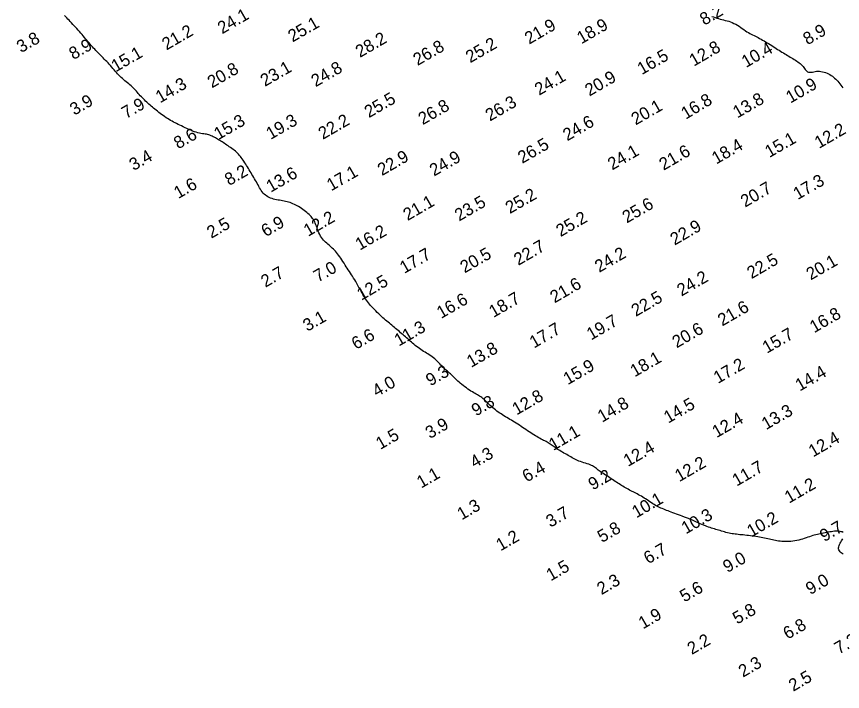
# Model space of a CAD drawing. Extents: x 3024098 to 3056816, y 418252 to 509144.
# Drawn here: x 3027058 to 3027391.3, y 419770.4 to 420042.8 of the extents above; entities that cross this region are included whole.
import ezdxf

# ---------------------------------------------------------------- set-up
doc = ezdxf.new("R2010")
doc.units = 0
doc.layers.add('V-CHAN-CONT-EL10', color=7, linetype='Continuous')
doc.layers.add('V-TOPO-SOUN-0911', color=7, linetype='Continuous')

msp = doc.modelspace()

# ---------------------------------------------------------------- linework, layer by layer
at = {"layer": 'V-CHAN-CONT-EL10'}
for points in [[(3027391.64, 419834.55), (3027391.28, 419834.72), (3027390.85, 419834.85), (3027390.38, 419834.95), (3027389.85, 419835.02), (3027389.29, 419835.04), (3027388.71, 419835.03), (3027388.12, 419834.99), (3027387.5, 419834.93), (3027386.88, 419834.85), (3027386.24, 419834.74), (3027385.61, 419834.63), (3027384.97, 419834.51), (3027384.34, 419834.39), (3027383.71, 419834.27), (3027383.09, 419834.15), (3027382.47, 419834.03), (3027381.85, 419833.9), (3027381.23, 419833.77), (3027380.6, 419833.61), (3027379.97, 419833.45), (3027379.33, 419833.26), (3027378.68, 419833.05), (3027378.02, 419832.82), (3027377.34, 419832.58), (3027376.65, 419832.34), (3027375.94, 419832.1), (3027375.22, 419831.87), (3027374.47, 419831.65), (3027373.71, 419831.46), (3027372.94, 419831.29), (3027372.14, 419831.14), (3027371.35, 419831.03), (3027370.55, 419830.94), (3027369.76, 419830.88), (3027368.98, 419830.84), (3027368.23, 419830.83), (3027367.5, 419830.85), (3027366.81, 419830.9), (3027366.14, 419830.97), (3027365.5, 419831.05), (3027364.88, 419831.16), (3027364.27, 419831.28), (3027363.67, 419831.41), (3027363.06, 419831.55), (3027362.45, 419831.69), (3027361.83, 419831.83), (3027361.2, 419831.97), (3027360.55, 419832.11), (3027359.9, 419832.25), (3027359.23, 419832.38), (3027358.54, 419832.51), (3027357.85, 419832.64), (3027357.14, 419832.76), (3027356.41, 419832.88), (3027355.67, 419832.99), (3027354.93, 419833.09), (3027354.19, 419833.19), (3027353.45, 419833.28), (3027352.71, 419833.36), (3027351.99, 419833.44), (3027351.29, 419833.51), (3027350.6, 419833.58), (3027349.93, 419833.64), (3027349.27, 419833.71), (3027348.64, 419833.78), (3027348.01, 419833.85), (3027347.39, 419833.93), (3027346.77, 419834.03), (3027346.16, 419834.14), (3027345.55, 419834.27), (3027344.94, 419834.42), (3027344.33, 419834.57), (3027343.73, 419834.74), (3027343.13, 419834.92), (3027342.54, 419835.09), (3027341.95, 419835.27), (3027341.37, 419835.44), (3027340.8, 419835.61), (3027340.23, 419835.77), (3027339.66, 419835.94), (3027339.08, 419836.11), (3027338.5, 419836.29), (3027337.9, 419836.48), (3027337.29, 419836.7), (3027336.65, 419836.93), (3027336, 419837.19), (3027335.31, 419837.47), (3027334.61, 419837.77), (3027333.89, 419838.08), (3027333.14, 419838.41), (3027332.38, 419838.75), (3027331.6, 419839.09), (3027330.8, 419839.43), (3027329.99, 419839.77), (3027329.17, 419840.11), (3027328.35, 419840.45), (3027327.53, 419840.77), (3027326.71, 419841.09), (3027325.91, 419841.4), (3027325.12, 419841.7), (3027324.37, 419841.98), (3027323.64, 419842.25), (3027322.93, 419842.5), (3027322.25, 419842.75), (3027321.6, 419842.99), (3027320.97, 419843.22), (3027320.36, 419843.45), (3027319.77, 419843.68), (3027319.19, 419843.91), (3027318.62, 419844.14), (3027318.07, 419844.39), (3027317.53, 419844.64), (3027316.98, 419844.9), (3027316.44, 419845.18), (3027315.9, 419845.48), (3027315.35, 419845.79), (3027314.8, 419846.13), (3027314.23, 419846.49), (3027313.66, 419846.86), (3027313.07, 419847.25), (3027312.49, 419847.65), (3027311.9, 419848.04), (3027311.32, 419848.43), (3027310.74, 419848.8), (3027310.18, 419849.15), (3027309.62, 419849.48), (3027309.07, 419849.78), (3027308.53, 419850.07), (3027307.99, 419850.34), (3027307.46, 419850.61), (3027306.93, 419850.87), (3027306.41, 419851.12), (3027305.89, 419851.39), (3027305.36, 419851.66), (3027304.84, 419851.95), (3027304.31, 419852.24), (3027303.79, 419852.53), (3027303.26, 419852.84), (3027302.74, 419853.15), (3027302.22, 419853.47), (3027301.7, 419853.8), (3027301.19, 419854.13), (3027300.67, 419854.47), (3027300.16, 419854.81), (3027299.64, 419855.16), (3027299.11, 419855.51), (3027298.57, 419855.87), (3027298.03, 419856.23), (3027297.47, 419856.59), (3027296.9, 419856.95), (3027296.32, 419857.32), (3027295.74, 419857.68), (3027295.17, 419858.04), (3027294.61, 419858.4), (3027294.09, 419858.74), (3027293.59, 419859.09), (3027293.14, 419859.42), (3027292.73, 419859.73), (3027292.36, 419860.04), (3027292.01, 419860.33), (3027291.66, 419860.61), (3027291.31, 419860.88), (3027290.93, 419861.14), (3027290.52, 419861.39), (3027290.05, 419861.62), (3027289.52, 419861.84), (3027288.93, 419862.05), (3027288.31, 419862.26), (3027287.65, 419862.47), (3027286.98, 419862.68), (3027286.31, 419862.89), (3027285.65, 419863.11), (3027285.01, 419863.35), (3027284.41, 419863.59), (3027283.83, 419863.85), (3027283.28, 419864.13), (3027282.75, 419864.41), (3027282.22, 419864.7), (3027281.7, 419865.01), (3027281.17, 419865.31), (3027280.63, 419865.63), (3027280.08, 419865.95), (3027279.51, 419866.27), (3027278.94, 419866.59), (3027278.38, 419866.92), (3027277.82, 419867.24), (3027277.28, 419867.56), (3027276.76, 419867.88), (3027276.27, 419868.2), (3027275.81, 419868.51), (3027275.38, 419868.81), (3027274.97, 419869.11), (3027274.58, 419869.4), (3027274.19, 419869.69), (3027273.81, 419869.96), (3027273.42, 419870.23), (3027273.02, 419870.49), (3027272.6, 419870.74), (3027272.16, 419870.98), (3027271.7, 419871.22), (3027271.22, 419871.46), (3027270.73, 419871.71), (3027270.22, 419871.98), (3027269.69, 419872.25), (3027269.14, 419872.55), (3027268.58, 419872.87), (3027268, 419873.21), (3027267.41, 419873.57), (3027266.8, 419873.94), (3027266.18, 419874.34), (3027265.55, 419874.74), (3027264.91, 419875.16), (3027264.26, 419875.59), (3027263.61, 419876.02), (3027262.95, 419876.46), (3027262.28, 419876.9), (3027261.62, 419877.33), (3027260.95, 419877.77), (3027260.29, 419878.2), (3027259.64, 419878.61), (3027259, 419879.02), (3027258.36, 419879.41), (3027257.74, 419879.79), (3027257.13, 419880.17), (3027256.52, 419880.53), (3027255.92, 419880.89), (3027255.33, 419881.26), (3027254.74, 419881.62), (3027254.16, 419881.99), (3027253.59, 419882.36), (3027253.02, 419882.74), (3027252.45, 419883.14), (3027251.89, 419883.54), (3027251.33, 419883.96), (3027250.79, 419884.4), (3027250.25, 419884.84), (3027249.71, 419885.31), (3027249.19, 419885.79), (3027248.68, 419886.28), (3027248.18, 419886.77), (3027247.68, 419887.26), (3027247.19, 419887.73), (3027246.72, 419888.17), (3027246.25, 419888.59), (3027245.8, 419888.97), (3027245.35, 419889.3), (3027244.91, 419889.59), (3027244.47, 419889.86), (3027244.02, 419890.12), (3027243.55, 419890.37), (3027243.07, 419890.64), (3027242.55, 419890.92), (3027242.01, 419891.23), (3027241.43, 419891.59), (3027240.82, 419891.98), (3027240.19, 419892.4), (3027239.55, 419892.84), (3027238.92, 419893.3), (3027238.29, 419893.78), (3027237.69, 419894.25), (3027237.12, 419894.73), (3027236.59, 419895.19), (3027236.1, 419895.65), (3027235.63, 419896.1), (3027235.19, 419896.54), (3027234.77, 419896.96), (3027234.36, 419897.37), (3027233.96, 419897.77), (3027233.56, 419898.15), (3027233.16, 419898.51), (3027232.75, 419898.87), (3027232.34, 419899.22), (3027231.93, 419899.58), (3027231.5, 419899.94), (3027231.07, 419900.32), (3027230.64, 419900.72), (3027230.19, 419901.15), (3027229.73, 419901.61), (3027229.27, 419902.09), (3027228.8, 419902.59), (3027228.31, 419903.1), (3027227.82, 419903.61), (3027227.31, 419904.11), (3027226.79, 419904.59), (3027226.26, 419905.04), (3027225.72, 419905.46), (3027225.17, 419905.84), (3027224.61, 419906.21), (3027224.04, 419906.56), (3027223.47, 419906.91), (3027222.9, 419907.25), (3027222.32, 419907.6), (3027221.75, 419907.97), (3027221.18, 419908.35), (3027220.61, 419908.76), (3027220.05, 419909.17), (3027219.5, 419909.6), (3027218.95, 419910.04), (3027218.42, 419910.48), (3027217.89, 419910.92), (3027217.38, 419911.35), (3027216.88, 419911.78), (3027216.39, 419912.21), (3027215.92, 419912.63), (3027215.44, 419913.04), (3027214.97, 419913.46), (3027214.5, 419913.88), (3027214.02, 419914.3), (3027213.54, 419914.72), (3027213.04, 419915.14), (3027212.54, 419915.57), (3027212.04, 419916.01), (3027211.53, 419916.44), (3027211.02, 419916.87), (3027210.5, 419917.3), (3027209.99, 419917.72), (3027209.49, 419918.15), (3027208.98, 419918.56), (3027208.48, 419918.98), (3027207.98, 419919.4), (3027207.47, 419919.82), (3027206.96, 419920.26), (3027206.44, 419920.72), (3027205.9, 419921.19), (3027205.35, 419921.69), (3027204.78, 419922.22), (3027204.2, 419922.77), (3027203.61, 419923.33), (3027203.03, 419923.91), (3027202.46, 419924.49), (3027201.91, 419925.06), (3027201.38, 419925.63), (3027200.89, 419926.18), (3027200.44, 419926.7), (3027200.03, 419927.22), (3027199.64, 419927.72), (3027199.27, 419928.24), (3027198.92, 419928.76), (3027198.56, 419929.32), (3027198.21, 419929.9), (3027197.84, 419930.53), (3027197.46, 419931.2), (3027197.06, 419931.92), (3027196.65, 419932.67), (3027196.23, 419933.44), (3027195.81, 419934.22), (3027195.37, 419934.99), (3027194.94, 419935.76), (3027194.5, 419936.5), (3027194.07, 419937.21), (3027193.65, 419937.9), (3027193.22, 419938.56), (3027192.79, 419939.21), (3027192.36, 419939.85), (3027191.93, 419940.49), (3027191.5, 419941.14), (3027191.07, 419941.79), (3027190.64, 419942.47), (3027190.2, 419943.15), (3027189.76, 419943.83), (3027189.32, 419944.51), (3027188.88, 419945.17), (3027188.44, 419945.81), (3027188, 419946.42), (3027187.57, 419946.99), (3027187.15, 419947.52), (3027186.73, 419948.01), (3027186.31, 419948.46), (3027185.89, 419948.89), (3027185.46, 419949.29), (3027185.03, 419949.69), (3027184.6, 419950.07), (3027184.15, 419950.45), (3027183.7, 419950.84), (3027183.24, 419951.24), (3027182.78, 419951.65), (3027182.33, 419952.08), (3027181.89, 419952.54), (3027181.47, 419953.03), (3027181.07, 419953.56), (3027180.71, 419954.13), (3027180.38, 419954.74), (3027180.08, 419955.39), (3027179.8, 419956.06), (3027179.55, 419956.74), (3027179.31, 419957.42), (3027179.07, 419958.08), (3027178.84, 419958.72), (3027178.6, 419959.32), (3027178.36, 419959.86), (3027178.1, 419960.37), (3027177.83, 419960.84), (3027177.53, 419961.27), (3027177.21, 419961.69), (3027176.87, 419962.09), (3027176.49, 419962.49), (3027176.08, 419962.89), (3027175.63, 419963.29), (3027175.15, 419963.7), (3027174.64, 419964.11), (3027174.11, 419964.52), (3027173.56, 419964.92), (3027173, 419965.31), (3027172.44, 419965.68), (3027171.86, 419966.03), (3027171.29, 419966.36), (3027170.72, 419966.67), (3027170.15, 419966.95), (3027169.58, 419967.21), (3027169, 419967.45), (3027168.42, 419967.66), (3027167.84, 419967.85), (3027167.24, 419968.01), (3027166.64, 419968.15), (3027166.03, 419968.28), (3027165.42, 419968.39), (3027164.8, 419968.49), (3027164.18, 419968.59), (3027163.56, 419968.7), (3027162.94, 419968.81), (3027162.33, 419968.95), (3027161.73, 419969.1), (3027161.13, 419969.29), (3027160.55, 419969.49), (3027159.99, 419969.74), (3027159.45, 419970.01), (3027158.94, 419970.33), (3027158.45, 419970.68), (3027157.99, 419971.08), (3027157.57, 419971.52), (3027157.18, 419972), (3027156.82, 419972.52), (3027156.47, 419973.07), (3027156.14, 419973.64), (3027155.81, 419974.22), (3027155.49, 419974.82), (3027155.16, 419975.42), (3027154.83, 419976.03), (3027154.48, 419976.63), (3027154.13, 419977.24), (3027153.77, 419977.84), (3027153.42, 419978.45), (3027153.05, 419979.05), (3027152.69, 419979.65), (3027152.33, 419980.26), (3027151.97, 419980.86), (3027151.61, 419981.46), (3027151.25, 419982.05), (3027150.89, 419982.64), (3027150.53, 419983.21), (3027150.18, 419983.77), (3027149.82, 419984.31), (3027149.46, 419984.84), (3027149.1, 419985.34), (3027148.74, 419985.82), (3027148.37, 419986.28), (3027147.99, 419986.73), (3027147.6, 419987.16), (3027147.19, 419987.57), (3027146.77, 419987.98), (3027146.34, 419988.37), (3027145.88, 419988.76), (3027145.4, 419989.13), (3027144.91, 419989.5), (3027144.41, 419989.86), (3027143.9, 419990.22), (3027143.4, 419990.56), (3027142.89, 419990.9), (3027142.39, 419991.22), (3027141.9, 419991.54), (3027141.43, 419991.85), (3027140.96, 419992.16), (3027140.49, 419992.45), (3027140.04, 419992.73), (3027139.59, 419993.01), (3027139.15, 419993.28), (3027138.72, 419993.54), (3027138.29, 419993.78), (3027137.85, 419994.02), (3027137.43, 419994.25), (3027136.99, 419994.46), (3027136.55, 419994.65), (3027136.1, 419994.82), (3027135.63, 419994.97), (3027135.15, 419995.1), (3027134.65, 419995.21), (3027134.14, 419995.3), (3027133.6, 419995.39), (3027133.03, 419995.47), (3027132.44, 419995.57), (3027131.83, 419995.69), (3027131.18, 419995.84), (3027130.51, 419996.03), (3027129.8, 419996.26), (3027129.07, 419996.54), (3027128.33, 419996.84), (3027127.58, 419997.17), (3027126.82, 419997.52), (3027126.07, 419997.87), (3027125.34, 419998.22), (3027124.63, 419998.57), (3027123.94, 419998.9), (3027123.29, 419999.22), (3027122.65, 419999.53), (3027122.03, 419999.84), (3027121.42, 420000.15), (3027120.82, 420000.47), (3027120.22, 420000.81), (3027119.62, 420001.16), (3027119.01, 420001.54), (3027118.4, 420001.93), (3027117.79, 420002.34), (3027117.19, 420002.76), (3027116.59, 420003.19), (3027116, 420003.63), (3027115.43, 420004.06), (3027114.88, 420004.49), (3027114.34, 420004.92), (3027113.83, 420005.34), (3027113.32, 420005.75), (3027112.84, 420006.17), (3027112.36, 420006.58), (3027111.9, 420006.99), (3027111.44, 420007.4), (3027111, 420007.81), (3027110.55, 420008.23), (3027110.11, 420008.65), (3027109.67, 420009.07), (3027109.24, 420009.5), (3027108.82, 420009.93), (3027108.4, 420010.36), (3027107.99, 420010.8), (3027107.58, 420011.24), (3027107.18, 420011.68), (3027106.79, 420012.12), (3027106.39, 420012.56), (3027106, 420013), (3027105.59, 420013.44), (3027105.17, 420013.88), (3027104.74, 420014.31), (3027104.29, 420014.73), (3027103.82, 420015.15), (3027103.33, 420015.57), (3027102.83, 420015.98), (3027102.32, 420016.4), (3027101.8, 420016.82), (3027101.28, 420017.25), (3027100.77, 420017.7), (3027100.27, 420018.16), (3027099.77, 420018.65), (3027099.29, 420019.15), (3027098.81, 420019.66), (3027098.34, 420020.19), (3027097.87, 420020.73), (3027097.4, 420021.27), (3027096.93, 420021.82), (3027096.45, 420022.37), (3027095.96, 420022.92), (3027095.47, 420023.46), (3027094.97, 420024), (3027094.47, 420024.54), (3027093.96, 420025.07), (3027093.46, 420025.6), (3027092.96, 420026.11), (3027092.46, 420026.61), (3027091.96, 420027.11), (3027091.47, 420027.59), (3027090.99, 420028.07), (3027090.51, 420028.55), (3027090.04, 420029.03), (3027089.57, 420029.51), (3027089.11, 420030), (3027088.65, 420030.5), (3027088.2, 420031.02), (3027087.75, 420031.54), (3027087.29, 420032.08), (3027086.84, 420032.62), (3027086.38, 420033.18), (3027085.92, 420033.75), (3027085.44, 420034.32), (3027084.96, 420034.91), (3027084.46, 420035.49), (3027083.94, 420036.08), (3027083.42, 420036.68), (3027082.89, 420037.27), (3027082.36, 420037.86), (3027081.83, 420038.44), (3027081.3, 420039.02), (3027080.77, 420039.59), (3027080.25, 420040.15), (3027079.74, 420040.69), (3027079.24, 420041.22), (3027078.76, 420041.73), (3027078.29, 420042.23), (3027077.83, 420042.71), (3027077.4, 420043.17)], [(3027338.68, 420042.81), (3027339.3, 420042.56), (3027339.95, 420042.33), (3027340.6, 420042.12), (3027341.27, 420041.92), (3027341.95, 420041.73), (3027342.64, 420041.56), (3027343.33, 420041.39), (3027344.04, 420041.21), (3027344.75, 420041.02), (3027345.46, 420040.81), (3027346.16, 420040.58), (3027346.87, 420040.31), (3027347.56, 420039.99), (3027348.25, 420039.63), (3027348.94, 420039.23), (3027349.6, 420038.8), (3027350.26, 420038.35), (3027350.91, 420037.9), (3027351.54, 420037.46), (3027352.16, 420037.03), (3027352.77, 420036.63), (3027353.36, 420036.26), (3027353.94, 420035.93), (3027354.51, 420035.62), (3027355.07, 420035.33), (3027355.64, 420035.05), (3027356.2, 420034.78), (3027356.77, 420034.5), (3027357.34, 420034.22), (3027357.92, 420033.91), (3027358.51, 420033.59), (3027359.11, 420033.26), (3027359.72, 420032.91), (3027360.32, 420032.55), (3027360.94, 420032.19), (3027361.55, 420031.81), (3027362.16, 420031.43), (3027362.77, 420031.05), (3027363.37, 420030.66), (3027363.98, 420030.27), (3027364.57, 420029.88), (3027365.17, 420029.5), (3027365.76, 420029.12), (3027366.34, 420028.75), (3027366.92, 420028.39), (3027367.49, 420028.04), (3027368.05, 420027.7), (3027368.61, 420027.37), (3027369.16, 420027.04), (3027369.71, 420026.72), (3027370.25, 420026.41), (3027370.79, 420026.09), (3027371.32, 420025.77), (3027371.85, 420025.45), (3027372.38, 420025.12), (3027372.89, 420024.79), (3027373.38, 420024.45), (3027373.85, 420024.09), (3027374.3, 420023.73), (3027374.71, 420023.35), (3027375.1, 420022.96), (3027375.44, 420022.54), (3027375.76, 420022.13), (3027376.06, 420021.72), (3027376.35, 420021.34), (3027376.63, 420020.99), (3027376.93, 420020.7), (3027377.25, 420020.46), (3027377.59, 420020.3), (3027377.96, 420020.23), (3027378.38, 420020.23), (3027378.82, 420020.28), (3027379.3, 420020.36), (3027379.8, 420020.47), (3027380.33, 420020.57), (3027380.89, 420020.64), (3027381.47, 420020.68), (3027382.06, 420020.66), (3027382.67, 420020.59), (3027383.29, 420020.47), (3027383.91, 420020.31), (3027384.52, 420020.1), (3027385.12, 420019.86), (3027385.7, 420019.59), (3027386.25, 420019.3), (3027386.77, 420018.98), (3027387.27, 420018.65), (3027387.73, 420018.29), (3027388.18, 420017.9), (3027388.62, 420017.49), (3027389.04, 420017.06), (3027389.45, 420016.6), (3027389.86, 420016.11), (3027390.27, 420015.6), (3027390.68, 420015.07), (3027391.11, 420014.54), (3027391.54, 420014.02)], [(3027391.68, 419825.83), (3027391.19, 419826.07), (3027390.75, 419826.36), (3027390.38, 419826.7), (3027390.09, 419827.06), (3027389.9, 419827.46), (3027389.8, 419827.88), (3027389.79, 419828.32), (3027389.85, 419828.78), (3027389.97, 419829.24), (3027390.15, 419829.72), (3027390.37, 419830.19), (3027390.63, 419830.66), (3027390.92, 419831.12), (3027391.21, 419831.57), (3027391.5, 419832)]]:
    msp.add_lwpolyline(points, dxfattribs=at)

# ---------------------------------------------------------------- texts
at = {"layer": 'V-TOPO-SOUN-0911'}
for s, rotation, p in [('8.2', 30, (3027335.58, 420039.03)), ('24.1 ', 30, (3027140.99, 420035.55)), ('25.1 ', 30, (3027169.41, 420032.24)), ('21.9 ', 30, (3027264.9, 420031.37)), ('18.9 ', 30, (3027285.96, 420031.5)), ('21.2 ', 30, (3027118.54, 420029.01)), ('8.9', 30, (3027377.23, 420031.11)), ('3.8', 30, (3027059.88, 420027.93)), ('28.2 ', 30, (3027196.62, 420026.02)), ('25.2 ', 30, (3027241.11, 420023.86)), ('8.9', 30, (3027081, 420025.14)), ('26.8 ', 30, (3027219.88, 420022.77)), ('12.8 ', 30, (3027331.33, 420022.48)), ('10.4 ', 30, (3027352.43, 420021.95)), ('15.1 ', 30, (3027098.08, 420020.2)), ('16.5 ', 30, (3027310.36, 420019.07)), ('20.8 ', 30, (3027136.88, 420013.72)), ('23.1 ', 30, (3027158.25, 420014.32)), ('24.8 ', 30, (3027178.74, 420014.18)), ('24.1 ', 30, (3027268.91, 420010.75)), ('20.9 ', 30, (3027289.21, 420010.41)), ('14.3 ', 30, (3027115.95, 420007.68)), ('10.9 ', 30, (3027370.31, 420007.58)), ('3.9', 30, (3027081.36, 420002.7)), ('25.5 ', 30, (3027200.22, 420001.68)), ('16.8 ', 31.0692, (3027328.1, 420001.07)), ('13.8 ', 30, (3027348.92, 420001.58)), ('7.9', 30, (3027102.26, 420001.32)), ('26.8 ', 30, (3027221.95, 419998.86)), ('26.3 ', 30, (3027249.05, 420000.33)), ('20.1 ', 30, (3027307.89, 419998.77)), ('15.3 ', 30, (3027139.5, 419992.82)), ('19.3 ', 30, (3027160.56, 419992.92)), ('22.2 ', 30, (3027181.63, 419992.95)), ('24.6 ', 30, (3027280.31, 419992.37)), ('8.6', 30, (3027123.29, 419989.09)), ('12.2 ', 30, (3027381.89, 419989.31)), ('15.1 ', 30, (3027361.83, 419985.62)), ('26.5 ', 30, (3027262.13, 419983.27)), ('24.1 ', 30, (3027298.41, 419980.6)), ('21.6 ', 30, (3027319.16, 419980.49)), ('18.4 ', 30, (3027340.39, 419982.98)), ('3.4', 30, (3027105.31, 419980.36)), ('22.9 ', 30, (3027205.51, 419978.32)), ('24.9 ', 30, (3027226.51, 419978.12)), ('8.2', 30, (3027143.83, 419974.32)), ('13.6 ', 30, (3027160.6, 419971.6)), ('17.1 ', 30, (3027185.02, 419972.17)), ('1.6', 30, (3027123.32, 419969.05)), ('17.3 ', 30, (3027373.26, 419968.64)), ('20.7 ', 30, (3027352.03, 419965.59)), ('25.2 ', 30, (3027257.12, 419963)), ('21.1 ', 30, (3027215.86, 419960.19)), ('23.5 ', 30, (3027236.64, 419959.98)), ('25.6 ', 30, (3027304.3, 419959.2)), ('12.2 ', 30, (3027175.69, 419953.81)), ('25.2 ', 30, (3027277.56, 419953.68)), ('2.5', 30, (3027136.64, 419953.03)), ('6.9', 30, (3027158.56, 419953.65)), ('16.2 ', 30, (3027196.56, 419948.23)), ('22.9 ', 30, (3027323.62, 419950.27)), ('22.7 ', 30, (3027260.53, 419942.1)), ('17.7 ', 30, (3027214.5, 419938.85)), ('20.5 ', 30, (3027238.87, 419939.05)), ('24.2 ', 30, (3027293.18, 419939.28)), ('22.5 ', 30, (3027354.62, 419936.72)), ('20.1 ', 30, (3027378.53, 419936.21)), ('2.7', 30, (3027158.46, 419933.25)), ('7.0', 30, (3027179.71, 419935.34)), ('12.5 ', 30, (3027197.2, 419928.02)), ('21.6 ', 30, (3027275.16, 419926.95)), ('24.2 ', 30, (3027326.35, 419929.7)), ('16.6 ', 30, (3027229.39, 419920.68)), ('18.7 ', 30, (3027250.49, 419921.07)), ('22.5 ', 30, (3027307.93, 419921.49)), ('21.6 ', 30, (3027342.81, 419917.63)), ('16.8 ', 30, (3027379.92, 419914.9)), ('3.1', 30, (3027175.41, 419915.48)), ('19.7 ', 30, (3027289.9, 419911.98)), ('11.3 ', 30, (3027212.3, 419909.52)), ('17.7 ', 30, (3027266.86, 419908.73)), ('20.6 ', 30, (3027324.44, 419908.8)), ('6.6', 30, (3027195.04, 419908.19)), ('15.7 ', 30, (3027360.83, 419906.63)), ('13.8 ', 30, (3027241.5, 419900.92)), ('15.9 ', 30, (3027280.48, 419893.94)), ('18.1 ', 30, (3027307.5, 419897.13)), ('17.2 ', 30, (3027341.11, 419894.46)), ('9.3', 30, (3027225.03, 419893.42)), ('14.4 ', 30, (3027374.11, 419891.38)), ('4.0', 30, (3027203.43, 419889.08)), ('12.8 ', 30, (3027259.84, 419881.73)), ('9.8', 30, (3027243.44, 419881.28)), ('14.8 ', 30, (3027294.32, 419878.78)), ('14.5 ', 30, (3027321.02, 419878.42)), ('13.3 ', 30, (3027360.5, 419875.79)), ('3.9', 30, (3027224.84, 419872.19)), ('12.4 ', 30, (3027340.55, 419872.58)), ('11.1 ', 30, (3027274.62, 419867.38)), ('1.5', 30, (3027204.85, 419867.83)), ('12.4 ', 30, (3027379.46, 419864.77)), ('12.4 ', 30, (3027304.76, 419860.93)), ('4.3', 30, (3027242.88, 419860.35)), ('12.2 ', 30, (3027325.49, 419854.8)), ('6.4', 30, (3027263.94, 419854.64)), ('11.7 ', 30, (3027348.65, 419853.02)), ('1.1', 30, (3027221.34, 419852.22)), ('9.2', 30, (3027290.58, 419851.42)), ('11.2 ', 30, (3027369.78, 419846.13)), ('1.3', 30, (3027237.66, 419839.38)), ('10.1 ', 30, (3027308.18, 419840.21)), ('3.7', 30, (3027273.49, 419836.4)), ('10.3 ', 30, (3027328.15, 419833.73)), ('10.2 ', 30, (3027354.59, 419832.49)), ('5.8', 30, (3027294.29, 419830.26)), ('9.7', 30, (3027383.99, 419830.59)), ('1.2', 30, (3027253.35, 419826.88)), ('6.7', 30, (3027312.93, 419821.63)), ('9.0', 30, (3027344.9, 419818.12)), ('1.5', 30, (3027273.61, 419814.78)), ('2.3', 30, (3027294.06, 419809.2)), ('9.0', 30, (3027378.33, 419809.23)), ('5.6', 30, (3027327.52, 419806.22)), ('5.8', 30, (3027348.85, 419797.32)), ('1.9', 30, (3027310.83, 419795.39)), ('6.8', 30, (3027369.19, 419791.22)), ('2.2', 30, (3027330.51, 419785.05)), ('7.2', 30, (3027389.89, 419785.22)), ('2.3', 30, (3027351.18, 419775.9)), ('2.5', 30, (3027371.45, 419770.19))]:
    msp.add_text(s, height=5, rotation=rotation, dxfattribs=at).set_placement(p)

doc.saveas('drawing.dxf')
